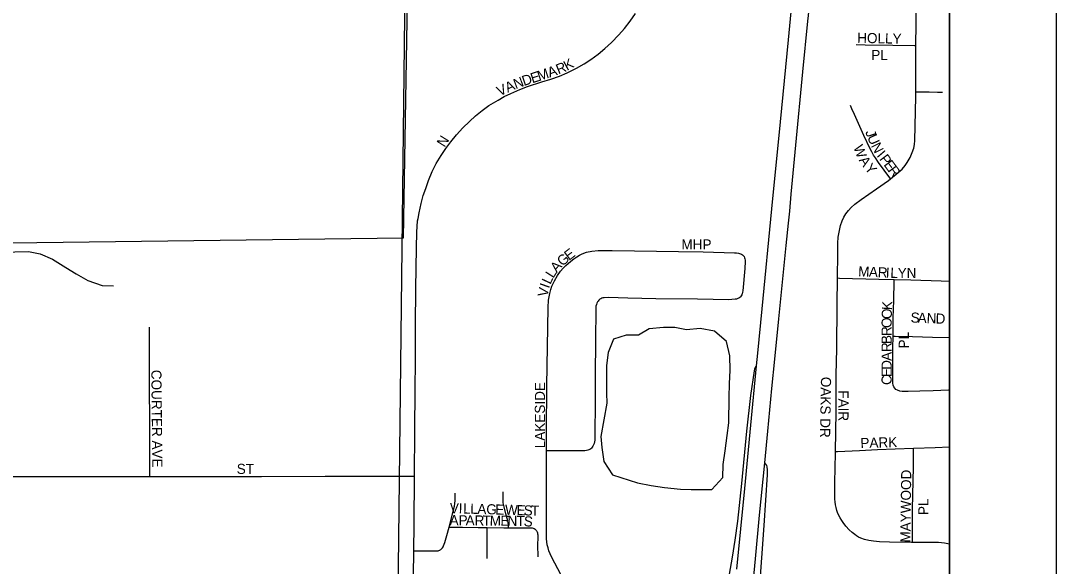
# Model space of a CAD drawing. Extents: x 0 to 1391, y -24 to 440.
# Drawn here: x 460.63 to 480, y 353.42 to 363.63 of the extents above; entities that cross this region are included whole.
import ezdxf

# ---------------------------------------------------------------- set-up
doc = ezdxf.new("R2010")
doc.units = 0
for name, color, linetype in [('GM_X_City_Street', 7, 'Continuous'), ('GM_X_City_Street_Text', 7, 'Continuous'), ('GM_X_Corporation', 7, 'Continuous'), ('GM_X_Interchange_Ramps', 7, 'Continuous'), ('GM_X_Interstate_Route', 7, 'Continuous'), ('GM_X_Minor_Lake', 7, 'Continuous'), ('GM_X_Minor_River', 7, 'Continuous'), ('GM_X_Section', 7, 'Continuous'), ('GM_X_Township', 7, 'Continuous'), ('SH_Data', 7, 'Continuous')]:
    doc.layers.add(name, color=color, linetype=linetype)

msp = doc.modelspace()

# ---------------------------------------------------------------- linework, layer by layer
at = {"layer": 'GM_X_City_Street'}
for points in [[(477.374, 363.163), (477.378, 363.572), (477.379, 363.833), (477.383, 364.243), (477.383, 364.265)], [(468.065, 359.927), (468.084, 360.033), (468.123, 360.208), (468.162, 360.356), (468.208, 360.492), (468.261, 360.638), (468.328, 360.805), (468.404, 360.956), (468.499, 361.107), (468.583, 361.235), (468.676, 361.362), (468.781, 361.495), (468.9, 361.622), (469.025, 361.744), (469.138, 361.851), (469.266, 361.951), (469.391, 362.042), (469.562, 362.145), (469.675, 362.211), (469.799, 362.269), (469.966, 362.341), (470.112, 362.396), (470.38, 362.483), (470.548, 362.537), (470.707, 362.593), (470.854, 362.654), (471.026, 362.741), (471.171, 362.824), (471.297, 362.901), (471.434, 363.004), (471.557, 363.106), (471.683, 363.223), (471.819, 363.365), (471.924, 363.485), (472.031, 363.62), (472.13, 363.761)], [(476.258, 363.181), (476.429, 363.178), (476.942, 363.169), (477.348, 363.163), (477.374, 363.163)], [(477.374, 362.296), (477.373, 362.592), (477.373, 363.075), (477.374, 363.163)], [(476.898, 360.671), (477.045, 360.786), (477.116, 360.853), (477.172, 360.917), (477.214, 360.976), (477.267, 361.072), (477.307, 361.161), (477.334, 361.242), (477.349, 361.313), (477.357, 361.385), (477.374, 362.205), (477.374, 362.296)], [(477.374, 362.296), (477.399, 362.296), (477.624, 362.295), (477.78, 362.293), (477.87, 362.291)], [(476.898, 360.671), (476.886, 360.686), (476.673, 360.975), (476.617, 361.06), (476.581, 361.114), (476.548, 361.173), (476.517, 361.23), (476.4, 361.478), (476.228, 361.871), (476.177, 361.982), (476.152, 362.045)], [(475.911, 358.809), (475.911, 358.829), (475.914, 359.252), (475.914, 359.365), (475.915, 359.464), (475.923, 359.577), (475.943, 359.701), (475.966, 359.799), (475.995, 359.883), (476.028, 359.953), (476.067, 360.018), (476.113, 360.08), (476.164, 360.136), (476.23, 360.195), (476.351, 360.285), (476.636, 360.485), (476.86, 360.641), (476.898, 360.671)], [(467.996, 355.105), (468.004, 355.956), (468.01, 356.722), (468.015, 357.272), (468.014, 357.927), (468.021, 358.619), (468.033, 359.382), (468.039, 359.675), (468.046, 359.78), (468.057, 359.887), (468.065, 359.927)], [(470.469, 355.581), (470.469, 355.939), (470.473, 356.797), (470.496, 358.264), (470.507, 358.402), (470.527, 358.525), (470.547, 358.598), (470.567, 358.66), (470.614, 358.764), (470.671, 358.863), (470.731, 358.944), (470.779, 358.998), (470.826, 359.046), (470.874, 359.089), (470.92, 359.129), (470.978, 359.171), (471.033, 359.209), (471.086, 359.239), (471.133, 359.264), (471.217, 359.296), (471.317, 359.319), (471.43, 359.33), (471.692, 359.332), (472.115, 359.326), (472.935, 359.309), (473.395, 359.302), (473.98, 359.288), (474.019, 359.285), (474.057, 359.279), (474.077, 359.275), (474.096, 359.268), (474.116, 359.258), (474.132, 359.247), (474.149, 359.23), (474.16, 359.215), (474.17, 359.195), (474.176, 359.175), (474.18, 359.15), (474.182, 359.121), (474.177, 358.995), (474.14, 358.572), (474.135, 358.547), (474.127, 358.52), (474.119, 358.5), (474.11, 358.483), (474.096, 358.465), (474.081, 358.451), (474.065, 358.44), (474.045, 358.429), (474.02, 358.421), (473.992, 358.416), (473.935, 358.41), (473.878, 358.408), (473.293, 358.416), (472.51, 358.427), (471.989, 358.439), (471.626, 358.447), (471.543, 358.445), (471.521, 358.443), (471.499, 358.437), (471.48, 358.427), (471.461, 358.416), (471.446, 358.401), (471.43, 358.384), (471.418, 358.366), (471.408, 358.345), (471.399, 358.32), (471.392, 358.29), (471.387, 358.168), (471.384, 357.709), (471.384, 357.559), (471.379, 357.079), (471.374, 356.59), (471.368, 355.781), (471.364, 355.747), (471.356, 355.716), (471.347, 355.69), (471.335, 355.666), (471.323, 355.649), (471.31, 355.633), (471.294, 355.62), (471.277, 355.607), (471.258, 355.598), (471.239, 355.591), (471.213, 355.585), (471.186, 355.581), (471.059, 355.58), (470.469, 355.581)], [(475.87, 355.568), (475.877, 355.934), (475.882, 356.319), (475.884, 356.729), (475.885, 357.002), (475.893, 357.487), (475.902, 358.32), (475.911, 358.809)], [(476.969, 358.781), (476.679, 358.788), (475.947, 358.808), (475.911, 358.809)], [(476.948, 357.728), (476.952, 358.072), (476.96, 358.394), (476.969, 358.759), (476.969, 358.781)], [(478, 358.751), (477.849, 358.757), (477.277, 358.774), (476.969, 358.781)], [(463.047, 355.1), (463.047, 355.148), (463.046, 355.53), (463.049, 355.879), (463.042, 357.024), (463.041, 357.895)], [(478, 356.717), (477.984, 356.716), (477.698, 356.706), (477.448, 356.696), (477.229, 356.688), (477.119, 356.693), (477.073, 356.699), (477.03, 356.714), (477.002, 356.731), (476.978, 356.754), (476.96, 356.781), (476.949, 356.812), (476.943, 356.846), (476.943, 356.981), (476.945, 357.154), (476.946, 357.502), (476.948, 357.728)], [(476.948, 357.728), (476.989, 357.727), (477.311, 357.719), (477.682, 357.71), (478, 357.701)], [(470.74, 353.253), (470.563, 353.595), (470.535, 353.655), (470.512, 353.712), (470.496, 353.765), (470.481, 353.822), (470.471, 353.88), (470.465, 353.935), (470.465, 354.482), (470.466, 354.919), (470.469, 355.581)], [(477.312, 353.868), (477.291, 353.868), (476.882, 353.869), (476.693, 353.877), (476.581, 353.888), (476.493, 353.904), (476.415, 353.924), (476.346, 353.949), (476.304, 353.966), (476.262, 353.993), (476.231, 354.017), (476.182, 354.055), (476.128, 354.102), (476.066, 354.171), (476.013, 354.24), (475.988, 354.275), (475.958, 354.325), (475.928, 354.382), (475.91, 354.424), (475.897, 354.465), (475.883, 354.518), (475.872, 354.571), (475.864, 354.627), (475.859, 354.678), (475.858, 354.74), (475.859, 354.989), (475.869, 355.536), (475.87, 355.568)], [(475.87, 355.568), (475.906, 355.569), (476.319, 355.585), (476.654, 355.603), (476.989, 355.62), (477.329, 355.632)], [(477.312, 353.868), (477.312, 353.894), (477.313, 354.497), (477.329, 355.277), (477.329, 355.598), (477.329, 355.632)], [(477.329, 355.632), (477.734, 355.646), (478, 355.656)], [(458.843, 355.102), (458.876, 355.102), (459.472, 355.101), (459.87, 355.099), (461.596, 355.101), (462.18, 355.101), (462.913, 355.1), (463.047, 355.1)], [(463.047, 355.1), (463.869, 355.102), (465.137, 355.103), (466.329, 355.106), (467.062, 355.109), (467.996, 355.105)], [(467.988, 353.707), (467.994, 354.201), (467.996, 355.105)], [(468.645, 354.155), (468.663, 354.223), (468.722, 354.451), (468.745, 354.543), (468.755, 354.595), (468.759, 354.651), (468.759, 354.788)], [(469.758, 354.141), (469.756, 354.175), (469.754, 354.198), (469.751, 354.233), (469.746, 354.269), (469.734, 354.317), (469.709, 354.404), (469.673, 354.535), (469.659, 354.607), (469.655, 354.669), (469.657, 354.816)], [(467.988, 353.707), (468.137, 353.707), (468.383, 353.707), (468.424, 353.709), (468.439, 353.711), (468.456, 353.716), (468.469, 353.721), (468.481, 353.727), (468.491, 353.735), (468.503, 353.746), (468.521, 353.768), (468.533, 353.787), (468.543, 353.805), (468.555, 353.832), (468.565, 353.864), (468.603, 353.994), (468.645, 354.155)], [(468.645, 354.155), (468.744, 354.155), (468.896, 354.155), (469.19, 354.149), (469.356, 354.146)], [(469.356, 353.569), (469.354, 353.832), (469.356, 354.052), (469.356, 354.146)], [(469.356, 354.146), (469.67, 354.141), (469.758, 354.141)], [(469.758, 354.141), (470.001, 354.138), (470.182, 354.138), (470.201, 354.137), (470.219, 354.133), (470.234, 354.126), (470.254, 354.115), (470.265, 354.105), (470.276, 354.092), (470.285, 354.078), (470.292, 354.063), (470.298, 354.045), (470.301, 354.028), (470.302, 354.007), (470.302, 353.984), (470.302, 353.956), (470.3, 353.819), (470.302, 353.598)], [(478, 353.836), (477.909, 353.852), (477.799, 353.864), (477.676, 353.868), (477.312, 353.868)], [(467.957, 349.636), (467.971, 350.311), (467.974, 351.318), (467.977, 352.505), (467.981, 353.243), (467.988, 353.707)]]:
    msp.add_lwpolyline(points, dxfattribs=at)
at = {"layer": 'GM_X_Corporation'}
msp.add_line((478, 308.53), (478, 378.802), dxfattribs=at)
msp.add_lwpolyline([(467.949, 369.191), (467.788, 359.563), (457.506, 359.432)], dxfattribs=at)
at = {"layer": 'GM_X_Interchange_Ramps'}
for points in [[(474.394, 357.17), (474.375, 357.152), (474.366, 357.139), (474.357, 357.118), (474.35, 357.079), (474.283, 356.616), (474.209, 355.949), (474.113, 354.972), (474.036, 354.267), (473.99, 353.91), (473.941, 353.59), (473.883, 353.272)], [(474.944, 349.616), (474.934, 349.734), (474.899, 349.892), (474.815, 350.217), (474.721, 350.578), (474.605, 351.048), (474.532, 351.376), (474.488, 351.608), (474.456, 351.829), (474.434, 352.04), (474.421, 352.276), (474.423, 352.549), (474.448, 352.971), (474.539, 354.186), (474.599, 355.134), (474.599, 355.223), (474.594, 355.284), (474.586, 355.307), (474.571, 355.334), (474.547, 355.359)]]:
    msp.add_lwpolyline(points, dxfattribs=at)
at = {"layer": 'GM_X_Interstate_Route'}
for points in [[(475.354, 363.621), (475.364, 363.725), (475.433, 364.443), (475.511, 365.222), (475.59, 366.026), (475.718, 367.337), (475.822, 368.413), (475.899, 369.175)], [(474.025, 353.365), (474.175, 354.874), (474.287, 356.062), (474.394, 357.17), (474.417, 357.41), (474.499, 358.239), (474.683, 360.106), (474.841, 361.739), (474.993, 363.273), (475.113, 364.522)], [(474.948, 359.42), (474.992, 359.841), (475.015, 360.064), (475.045, 360.385), (475.128, 361.301), (475.262, 362.674), (475.354, 363.621)], [(473.977, 349.485), (473.991, 349.618), (474.024, 349.935), (474.104, 350.776), (474.144, 351.184), (474.173, 351.481), (474.193, 351.679), (474.268, 352.458), (474.374, 353.559), (474.449, 354.376), (474.547, 355.359), (474.605, 355.946), (474.683, 356.75), (474.737, 357.294), (474.812, 358.049), (474.916, 359.112), (474.948, 359.42)]]:
    msp.add_lwpolyline(points, dxfattribs=at)
at = {"layer": 'GM_X_Minor_Lake'}
for points in [[(473.884, 356.585), (473.888, 356.835), (473.9, 357.092), (473.897, 357.357), (473.833, 357.624), (473.609, 357.818), (473.343, 357.869), (473.085, 357.844), (472.865, 357.886), (472.652, 357.89), (472.386, 357.866), (472.186, 357.748), (471.958, 357.746), (471.721, 357.667), (471.618, 357.419), (471.591, 357.177), (471.586, 356.935), (471.589, 356.662), (471.594, 356.472)], [(471.594, 356.472), (471.484, 355.846), (471.503, 355.641), (471.536, 355.382), (471.699, 355.129), (472.168, 354.983), (472.426, 354.932), (472.676, 354.897), (472.972, 354.861), (473.169, 354.857), (473.367, 354.86), (473.557, 354.856), (473.766, 355.079), (473.77, 355.322), (473.805, 355.578), (473.848, 355.866), (473.875, 356.107), (473.884, 356.585)]]:
    msp.add_lwpolyline(points, dxfattribs=at)
at = {"layer": 'GM_X_Minor_River'}
msp.add_lwpolyline([(457.466, 361.082), (457.739, 361.001), (457.948, 360.762), (458.05, 360.472), (458.041, 359.918), (458.091, 359.689), (458.217, 359.49), (458.472, 359.258), (458.676, 359.163), (458.927, 359.114), (459.155, 359.11), (459.361, 359.122), (459.605, 359.14), (459.841, 359.182), (460.269, 359.266), (460.521, 359.307), (460.78, 359.311), (461, 359.269), (461.227, 359.166), (461.475, 359.01), (461.671, 358.893), (461.89, 358.768), (462.155, 358.673), (462.368, 358.669)], dxfattribs=at)
at = {"layer": 'GM_X_Section'}
msp.add_line((478, 349.585), (478, 369.119), dxfattribs=at)
msp.add_lwpolyline([(467.874, 369.141), (467.652, 349.609), (447.184, 349.582), (447.056, 369.114)], close=True, dxfattribs=at)
msp.add_lwpolyline([(478, 369.119), (467.874, 369.141), (467.652, 349.609), (478, 349.585)], dxfattribs=at)
at = {"layer": 'GM_X_Township'}
msp.add_lwpolyline([(478, 305.116), (478, 388.948)], dxfattribs=at)
at = {"layer": 'SH_Data'}
for p, q in [((480, 420), (480, 280)), ((478, 418), (478, 282))]:
    msp.add_line(p, q, dxfattribs=at)

# ---------------------------------------------------------------- texts
at = {"layer": 'GM_X_City_Street_Text'}
for s, height, rotation, p in [('HOLLY', 0.1894, 358.7518, (476.275, 363.215)), ('K', 0.189, 28.4854, (470.849, 362.688)), ('PL', 0.1894, 0, (476.54, 362.893)), ('M', 0.189, 18.1695, (470.329, 362.499)), ('A', 0.189, 19.8023, (470.525, 362.563)), ('R', 0.189, 21.9303, (470.689, 362.622)), ('N', 0.189, 20.7582, (469.89, 362.347)), ('D', 0.189, 18.0686, (470.043, 362.406)), ('E', 0.189, 17.9424, (470.202, 362.457)), ('V', 0.189, 25.0697, (469.59, 362.211)), ('A', 0.189, 23.9248, (469.74, 362.281)), ('N', 0.189, 57.9872, (468.56, 361.248)), ('J', 0.189, 287.813, (476.426, 361.551)), ('U', 0.189, 293.7445, (476.459, 361.452)), ('W', 0.189, 290.9023, (476.201, 361.263)), ('N', 0.189, 296.6144, (476.53, 361.291)), ('I', 0.189, 310.456, (476.632, 361.101)), ('A', 0.189, 303.9894, (476.3, 361.018)), ('P', 0.189, 306.7606, (476.684, 361.04)), ('E', 0.189, 306.4492, (476.763, 360.933)), ('Y', 0.189, 309.5193, (476.405, 360.864)), ('R', 0.189, 306.4901, (476.843, 360.826)), ('MHP', 0.1894, 0, (472.99, 359.348)), ('G', 0.189, 41.2723, (470.765, 359.025)), ('E', 0.189, 37.1322, (470.887, 359.133)), ('A', 0.189, 48.2321, (470.658, 358.905)), ('L', 0.189, 57.3025, (470.591, 358.799)), ('M', 0.189, 357.2304, (476.292, 358.847)), ('A', 0.189, 357.2232, (476.492, 358.838)), ('R', 0.189, 357.2245, (476.658, 358.83)), ('I', 0.189, 357.2318, (476.808, 358.822)), ('L', 0.189, 358.4114, (476.895, 358.818)), ('Y', 0.189, 359.8687, (477.034, 358.815)), ('N', 0.189, 359.9929, (477.201, 358.814)), ('I', 0.189, 70.5697, (470.512, 358.61)), ('L', 0.189, 64.9138, (470.538, 358.684)), ('V', 0.189, 80.8251, (470.487, 358.455)), ('K', 0.189, 87.3111, (476.927, 358.21)), ('O', 0.189, 88.0981, (476.922, 358.044)), ('S', 0.189, 357.8961, (477.273, 357.982)), ('A', 0.189, 357.8797, (477.406, 357.977)), ('N', 0.189, 357.8874, (477.573, 357.97)), ('D', 0.189, 357.8797, (477.74, 357.964)), ('O', 0.189, 89.8251, (476.921, 357.879)), ('R', 0.189, 89.9757, (476.921, 357.729)), ('B', 0.189, 89.994, (476.921, 357.579)), ('PL', 0.1894, 90, (477.243, 357.496)), ('R', 0.189, 89.9757, (476.921, 357.429)), ('A', 0.189, 89.9781, (476.921, 357.263)), ('D', 0.189, 89.9928, (476.921, 357.096)), ('E', 0.189, 89.9727, (476.921, 356.963)), ('COURTER AVE', 0.18939, 270.5961, (463.076, 357.096)), ('OAKS DR', 0.1894, 269.0765, (475.6, 356.967)), ('C', 0.189, 90, (476.921, 356.813)), ('LAKESIDE', 0.1894, 90, (470.438, 355.629)), ('FAIR', 0.1894, 270, (475.926, 356.713)), ('PARK', 0.1894, 1.5474, (476.339, 355.632)), ('ST', 0.1894, 0, (464.674, 355.148)), ('MAYWOOD', 0.1894, 89.2576, (477.271, 353.862)), ('V', 0.189, 358.3166, (468.656, 354.415)), ('I', 0.189, 358.3056, (468.822, 354.41)), ('L', 0.189, 358.3057, (468.906, 354.408)), ('L', 0.189, 358.3057, (469.039, 354.404)), ('PL', 0.1894, 90, (477.61, 354.379)), ('A', 0.189, 358.3151, (469.172, 354.4)), ('G', 0.189, 358.3151, (469.339, 354.395)), ('E', 0.189, 358.323, (469.505, 354.39)), ('W', 0.189, 358.3152, (469.689, 354.385)), ('E', 0.189, 358.3057, (469.905, 354.378)), ('S', 0.189, 358.3057, (470.038, 354.374)), ('T', 0.189, 358.323, (470.172, 354.37)), ('A', 0.189, 359.3879, (468.654, 354.189)), ('P', 0.189, 359.3928, (468.821, 354.187)), ('A', 0.189, 359.3846, (468.954, 354.186)), ('R', 0.189, 359.3885, (469.121, 354.184)), ('T', 0.189, 359.3989, (469.271, 354.182)), ('M', 0.189, 359.3808, (469.404, 354.181)), ('E', 0.189, 359.3928, (469.604, 354.179)), ('N', 0.189, 359.3846, (469.738, 354.178)), ('T', 0.189, 359.0984, (469.904, 354.176)), ('S', 0.189, 354.8303, (470.034, 354.174))]:
    msp.add_text(s, height=height, rotation=rotation, dxfattribs=at).set_placement(p)

doc.saveas('drawing.dxf')
